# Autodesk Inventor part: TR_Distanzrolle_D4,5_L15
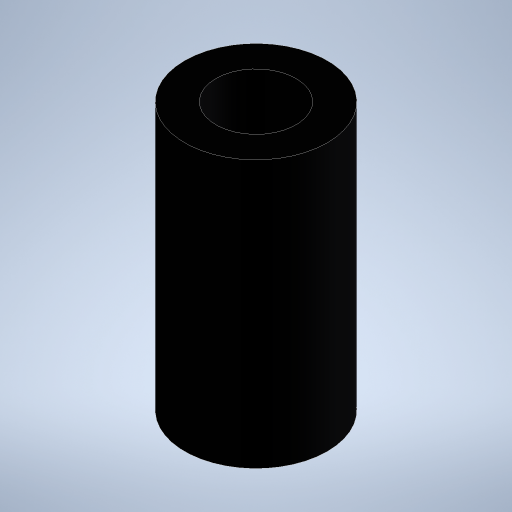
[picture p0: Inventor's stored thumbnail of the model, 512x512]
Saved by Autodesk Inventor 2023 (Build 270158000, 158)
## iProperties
Created: 2023-11
Part Number: TR_Distanzrolle_D4,5_L15
Material: PC/ABS-Kunststoff
Document SubType Name: Modeling
Designer: Admin
Density: 0.357273 g/cm^3
Appearance: Glatt - Schwarz
Author: Admin
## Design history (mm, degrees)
sketch "Skizze1"
  geometry: C1 r 2.25 at (0, 0); C2 r 4 at (0, 0); 1 further point
  constraints: 2 centre point, 2 coincident
  dimensions: "d0" = 4.5 diameter of C1; "d1" = 8 diameter of C2
extrude "Extrusion1" new body sketch "Skizze1" distance "d2" = 15; taper "d3" = 0 deg
node "Volumenkörper1"
